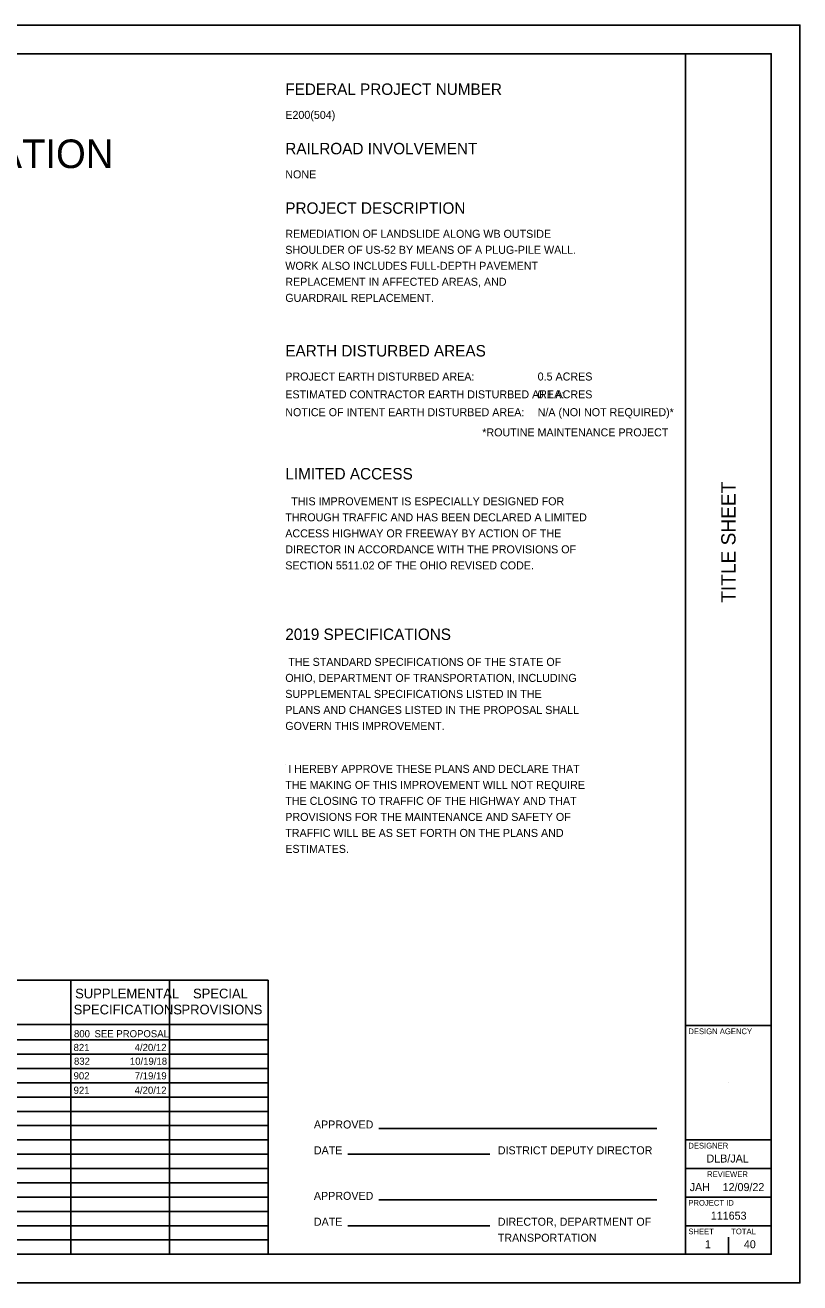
# Model space of a CAD drawing. Extents: x 0 to 34, y 0 to 22.
# Drawn here: x 20.45 to 34, y 0 to 22 of the extents above; entities that cross this region are included whole.
import ezdxf

# ---------------------------------------------------------------- set-up
doc = ezdxf.new("R2010")
doc.units = 0
for name, color, linetype in [('SH_Border', 7, 'Continuous'), ('SH_Cut_Line', 7, 'Continuous'), ('SH_Data', 7, 'Continuous'), ('SH_Text', 7, 'Continuous')]:
    doc.layers.add(name, color=color, linetype=linetype)

msp = doc.modelspace()

# ---------------------------------------------------------------- linework, layer by layer
at = {"layer": 'SH_Cut_Line'}
for p, q in [((25, 9.06), (25, 9.06)), ((11.25, 5.292), (24.7, 5.292)), ((21.25, 0.5), (21.25, 5.292)), ((22.975, 0.5), (22.975, 5.292)), ((24.7, 0.5), (24.7, 5.292)), ((11.25, 4.521), (24.7, 4.521)), ((11.25, 4.25), (24.7, 4.25)), ((11.25, 4), (24.7, 4)), ((11.25, 3.75), (24.7, 3.75)), ((11.25, 3.5), (24.7, 3.5)), ((32.75, 3.5), (32.75, 3.5)), ((11.25, 3.25), (24.7, 3.25)), ((11.25, 3), (24.7, 3)), ((11.25, 2.75), (24.7, 2.75)), ((26.635, 2.7), (31.5, 2.7)), ((11.25, 2.5), (24.7, 2.5)), ((11.25, 2.25), (24.7, 2.25)), ((26.091, 2.248), (28.576, 2.248)), ((11.25, 2), (24.7, 2)), ((11.25, 1.75), (24.7, 1.75)), ((11.25, 1.5), (24.7, 1.5)), ((26.635, 1.452), (31.5, 1.452)), ((11.25, 1.25), (24.7, 1.25)), ((11.25, 1), (24.7, 1)), ((26.091, 0.999), (28.576, 0.999)), ((11.25, 0.75), (24.7, 0.75)), ((32.375, 0.675), (32.375, 0.675)), ((32.75, 0.5), (32.75, 0.8))]:
    msp.add_line(p, q, dxfattribs=at)
at = {"layer": 'SH_Data'}
for p, q in [((32, 0.5), (32, 21.5)), ((32, 4.5), (33.5, 4.5)), ((32, 2.5), (33.5, 2.5)), ((32, 2), (33.5, 2)), ((32, 1.5), (33.5, 1.5)), ((32, 1), (33.5, 1))]:
    msp.add_line(p, q, dxfattribs=at)
msp.add_lwpolyline([(1.5, 21.5), (33.5, 21.5), (33.5, 0.5), (1.5, 0.5)], close=True, dxfattribs=at)
at = {"layer": 'SH_Text'}
msp.add_lwpolyline([(0, 0), (34, 0), (34, 22), (0, 22)], close=True, dxfattribs=at)

# ---------------------------------------------------------------- texts
at = {"layer": 'SH_Border'}
for s, height, p in [('FEDERAL PROJECT NUMBER', 0.2, (25, 20.78)), ('E200(504)', 0.14, (25, 20.36)), ('DEPARTMENT OF TRANSPORTATION', 0.5, (9.92, 19.5)), ('RAILROAD INVOLVEMENT', 0.2, (25, 19.741)), ('NONE', 0.14, (25, 19.32)), ('PROJECT DESCRIPTION', 0.2, (25, 18.7)), ('REMEDIATION OF LANDSLIDE ALONG WB OUTSIDE', 0.14, (25, 18.28)), ('SHOULDER OF US-52 BY MEANS OF A PLUG-PILE WALL.', 0.14, (25, 18)), ('WORK ALSO INCLUDES FULL-DEPTH PAVEMENT', 0.14, (25, 17.72)), ('REPLACEMENT IN AFFECTED AREAS, AND', 0.14, (25, 17.441)), ('GUARDRAIL REPLACEMENT.', 0.14, (25, 17.16)), ('EARTH DISTURBED AREAS', 0.2, (25, 16.204)), ('PROJECT EARTH DISTURBED AREA:', 0.14, (25, 15.784)), ('0.5 ACRES', 0.14, (29.414, 15.784)), ('ESTIMATED CONTRACTOR EARTH DISTURBED AREA:', 0.14, (25, 15.472)), ('0.1 ACRES', 0.14, (29.414, 15.472)), ('NOTICE OF INTENT EARTH DISTURBED AREA:', 0.14, (25, 15.16)), ('N/A (NOI NOT REQUIRED)*', 0.14, (29.414, 15.16)), ('*ROUTINE MAINTENANCE PROJECT', 0.14, (28.445, 14.807)), ('LIMITED ACCESS', 0.2, (25, 14.053)), ('  THIS IMPROVEMENT IS ESPECIALLY DESIGNED FOR', 0.14, (25, 13.601)), ('THROUGH TRAFFIC AND HAS BEEN DECLARED A LIMITED', 0.14, (25, 13.321)), ('ACCESS HIGHWAY OR FREEWAY BY ACTION OF THE', 0.14, (25, 13.04)), ('DIRECTOR IN ACCORDANCE WITH THE PROVISIONS OF', 0.14, (25, 12.761)), ('SECTION 5511.02 OF THE OHIO REVISED CODE.', 0.14, (25, 12.48)), ('2019 SPECIFICATIONS', 0.2, (25, 11.245)), (' THE STANDARD SPECIFICATIONS OF THE STATE OF', 0.14, (25, 10.792)), ('OHIO, DEPARTMENT OF TRANSPORTATION, INCLUDING', 0.14, (25, 10.512)), ('SUPPLEMENTAL SPECIFICATIONS LISTED IN THE', 0.14, (25, 10.232)), ('PLANS AND CHANGES LISTED IN THE PROPOSAL SHALL', 0.14, (25, 9.952)), ('GOVERN THIS IMPROVEMENT.', 0.14, (25, 9.672)), ('SUPPLEMENTAL', 0.17, (21.324, 4.976)), ('SPECIAL', 0.17, (23.386, 4.976)), ('SPECIFICATIONS', 0.17, (21.298, 4.696)), ('PROVISIONS', 0.17, (23.184, 4.696)), ('800', 0.125, (21.304, 4.295)), ('SEE PROPOSAL', 0.125, (21.664, 4.295)), ('821', 0.125, (21.297, 4.055)), ('4/20/12', 0.125, (22.365, 4.055)), ('832', 0.125, (21.304, 3.814)), ('10/19/18', 0.125, (22.282, 3.814)), ('902', 0.125, (21.297, 3.559)), ('7/19/19', 0.125, (22.367, 3.559)), ('921', 0.125, (21.297, 3.307)), ('4/20/12', 0.125, (22.365, 3.307)), ('APPROVED', 0.14, (25.5, 2.7)), ('DATE', 0.14, (25.5, 2.248)), ('DISTRICT DEPUTY DIRECTOR', 0.14, (28.717, 2.248)), ('APPROVED', 0.14, (25.5, 1.452)), ('DATE', 0.14, (25.5, 0.999)), ('DIRECTOR, DEPARTMENT OF', 0.14, (28.717, 0.999)), ('TRANSPORTATION', 0.14, (28.717, 0.719))]:
    msp.add_text(s, height=height, dxfattribs=at).set_placement(p)
at = {"layer": 'SH_Cut_Line'}
msp.add_text('TITLE SHEET', height=0.25, rotation=90, dxfattribs=at).set_placement((32.875, 11.897))
for s, height, p in [(' I HEREBY APPROVE THESE PLANS AND DECLARE THAT', 0.14, (25, 8.921)), ('THE MAKING OF THIS IMPROVEMENT WILL NOT REQUIRE', 0.14, (25, 8.64)), ('THE CLOSING TO TRAFFIC OF THE HIGHWAY AND THAT', 0.14, (25, 8.361)), ('PROVISIONS FOR THE MAINTENANCE AND SAFETY OF', 0.14, (25, 8.08)), ('TRAFFIC WILL BE AS SET FORTH ON THE PLANS AND', 0.14, (25, 7.8)), ('ESTIMATES.', 0.14, (25, 7.521)), ('DESIGN AGENCY', 0.1, (32.05, 4.35)), ('DESIGNER', 0.1, (32.05, 2.35)), ('DLB/JAL', 0.14, (32.368, 2.105)), ('REVIEWER', 0.1, (32.378, 1.85)), ('JAH', 0.14, (32.073, 1.605)), ('12/09/22', 0.14, (32.65, 1.605)), ('PROJECT ID', 0.1, (32.05, 1.35)), ('111653', 0.14, (32.443, 1.105)), ('SHEET', 0.1, (32.05, 0.85)), ('TOTAL', 0.1, (32.8, 0.85)), ('1', 0.14, (32.339, 0.605)), ('40', 0.14, (33.021, 0.605))]:
    msp.add_text(s, height=height, dxfattribs=at).set_placement(p)

doc.saveas('drawing.dxf')
